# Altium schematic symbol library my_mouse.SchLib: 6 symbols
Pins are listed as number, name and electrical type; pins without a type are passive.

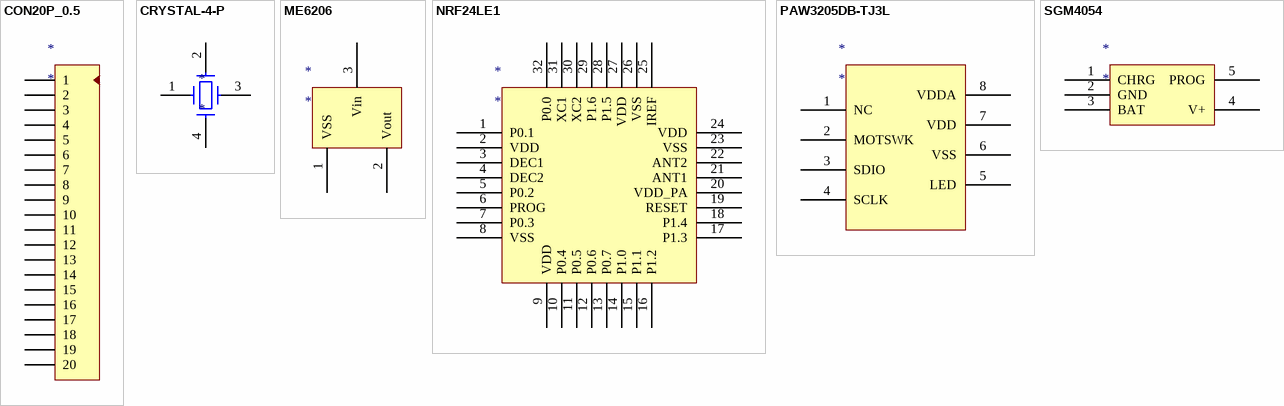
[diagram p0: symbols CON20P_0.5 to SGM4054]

## CON20P_0.5
designator *
pins: 1, 2, 3, 4, 5, 6, 7, 8, 9, 10, 11, 12, 13, 14, 15, 16, 17, 18, 19, 20

## CRYSTAL-4-P
designator *
footprint OSC3225
pins: 1, 2, 3, 4

## ME6206
designator *
footprint SOT95P245X110-3N (SOT23, 3-Leads, Body 2.90x2.45mm, Pitch 0.95mm, IPC Medium Density)
pins: 1 VSS, 2 Vout, 3 Vin

## NRF24LE1
designator *
footprint NRF24LE1 (QFN, 32-Leads, Body 5.00x5.00mm, Pitch 0.50mm, Thermal Pad 4.00x2.20mm, IPC Medium Density)
pins: 1 P0.1, 2 VDD, 3 DEC1, 4 DEC2, 5 P0.2, 6 PROG, 7 P0.3, 8 VSS, 9 VDD, 10 P0.4, 11 P0.5, 12 P0.6, 13 P0.7, 14 P1.0, 15 P1.1, 16 P1.2, 17 P1.3, 18 P1.4, 19 RESET, 20 VDD_PA, 21 ANT1, 22 ANT2, 23 VSS, 24 VDD, 25 IREF, 26 VSS, 27 VDD, 28 P1.5, 29 P1.6, 30 XC2, 31 XC1, 32 P0.0

## PAW3205DB-TJ3L
designator *
footprint PAW3205DB
pins: 1 NC, 2 MOTSWK, 3 SDIO, 4 SCLK, 5 LED, 6 VSS, 7 VDD, 8 VDDA

## SGM4054
designator *
footprint SGM4054
pins: 1 CHRG, 2 GND, 3 BAT, 4 V+, 5 PROG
